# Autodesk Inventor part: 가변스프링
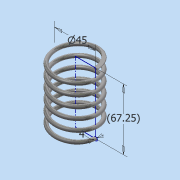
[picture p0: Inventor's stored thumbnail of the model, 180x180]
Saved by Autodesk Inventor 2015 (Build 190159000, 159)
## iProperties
Created: 2016-02
Part Number: 가변스프링
Material: 스테인레스 스틸
Document SubType Name: Modeling
Designer: Administrator
Mass: 84.1975 g
Surface Area: 106.451 cm^2
Volume: 10.5247 cm^3
Density: 8 g/cm^3
Appearance: 반연마
Author: Administrator
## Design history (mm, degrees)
sketch "스케치1"
  geometry: L1 (0, 0)-(-22.5, 0); L2 (-22.5, 0)-(-22.5, 67.25); L3 (-22.5, 67.25)-(0, 67.25); L4 (0, 67.25)-(0, 0); C1 r 2 at (-22.5, 0)
  constraints: 8 end point, 2 parallel, 1 centre point, 1 coincident, 1 horizontal, 1 perpendicular
  dimensions: "d0" = 67.25 distance of L1.end L2.end (derived); "d1" = 45 diameter of L2 L4; "d2" = 4 diameter of C1
feature "코일1" sketch "스케치1" pitch "d3" = 10; turns "d5" = 6; dims "d4" = 67.25 (= d0), "d6" = 0, angle "d7" = 90 deg, angle "d8" = 90 deg, "d9" = 0, "d10" = 0
sketch "스케치2"
  geometry: L1 (20.5, 0)-(24.5, 0) reference; 1 further point
  constraints: 1 horizontal alignment
extrude "돌출1" cut sketch "스케치2" stored distance "d11" = 10; taper "d12" = 0 deg
node "작업 평면1"
sketch "스케치3"
  geometry: L1 (2, 0)-(-2, 0) reference; 1 further point
  constraints: 1 horizontal alignment
extrude "돌출2" cut sketch "스케치3" stored distance "d13" = 10; taper "d14" = 0 deg
node "솔리드1"
node "절단 모서리 투영1"
node "절단 모서리 투영2"
